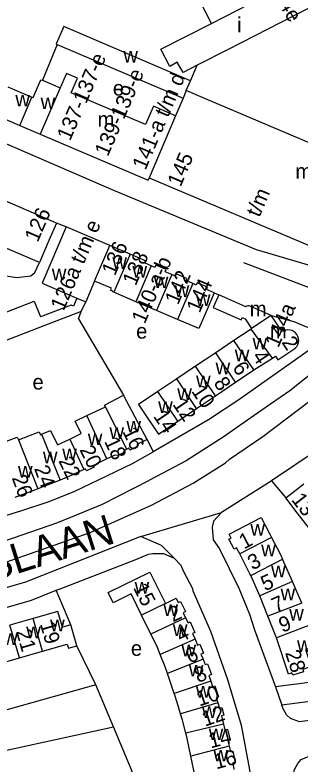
# Model space of a CAD drawing. Extents: x 161141 to 163125, y 381621 to 383200.
# Drawn here: x 162277.6 to 162353, y 382444.3 to 382642.8 of the extents above; entities that cross this region are included whole.
import ezdxf

# ---------------------------------------------------------------- set-up
doc = ezdxf.new("R2010")
doc.units = 0
for name, color, linetype in [('BLT_Basislijn', 7, 'Continuous'), ('BLT_Bebouwing', 7, 'Continuous'), ('BLT_Centroide', 7, 'Continuous'), ('BLT_Huisnummer', 7, 'Continuous'), ('BLT_Huisnummer_ tussenligend', 7, 'Continuous'), ('BLT_Huisnummer_reeks', 7, 'Continuous'), ('BLT_Onderdoorgang_en_onderverdeling', 7, 'Continuous'), ('BLT_Onderverdeling_panden', 7, 'Continuous'), ('BLT_Straatnaam_hoofdweg', 7, 'Continuous'), ('BLT_Vlakafsluiter', 7, 'Continuous')]:
    doc.layers.add(name, color=color, linetype=linetype)

msp = doc.modelspace()

# ---------------------------------------------------------------- linework, layer by layer
at = {"layer": 'BLT_Basislijn'}
for p, q in [((162288.77, 382634.99), (162284.83, 382625.47)), ((162324.01, 382625.3), (162325.78, 382629.45)), ((162291.14, 382586.62), (162288.54, 382587.63)), ((162338.06, 382577.23), (162368.49, 382565.55)), ((162330.3, 382569.18), (162331.49, 382568.61)), ((162294.42, 382562.3), (162295.1, 382564.25)), ((162294.42, 382562.3), (162306.27, 382542.03)), ((162312.57, 382530.29), (162314.16, 382527.02)), ((162345.48, 382519.35), (162349.25, 382514.86)), ((162288.51, 382490.36), (162289.53, 382490.77)), ((162292.32, 382481.23), (162288.51, 382490.36)), ((162298.98, 382465.34), (162293.93, 382475.68)), ((162303.64, 382454.22), (162298.98, 382465.34)), ((162346.52, 382464.77), (162348.22, 382459.93)), ((162255.7, 382443.65), (162303.64, 382454.22)), ((162314.81, 382427.53), (162303.64, 382454.22))]:
    msp.add_line(p, q, dxfattribs=at)
for points in [[(162377.15, 382570.34), (162374.71, 382570.72), (162341.47, 382580.52), (162303.7, 382596.26), (162245.74, 382621.4), (162216.51, 382633.67)], [(162270.38, 382574.4), (162278.09, 382573.22), (162281.73, 382573.67), (162282.87, 382574.53), (162284.03, 382577.2)], [(162345.42, 382563.14), (162351.37, 382561.53), (162356.87, 382559.29)], [(162359.01, 382556.56), (162337.09, 382541.02), (162328.81, 382535.56), (162314.16, 382527.02)], [(162362.6, 382553.21), (162361.54, 382552.11), (162350.35, 382543.18), (162342.61, 382537.88), (162332.63, 382530.95), (162322.85, 382524.63), (162313.17, 382519.51)], [(162080.89, 382389.1), (162087.08, 382392.8), (162096.77, 382401.05), (162097.06, 382401.61), (162097.92, 382402.29), (162103.21, 382407.77), (162109.43, 382414.56), (162120.5, 382427.73), (162125.96, 382433.33), (162133.78, 382441.38), (162141.36, 382447.96), (162147.08, 382452.5), (162159.07, 382460.25), (162172.83, 382467.15), (162180.96, 382470.1), (162190.27, 382472.7), (162275.19, 382497.81), (162297.47, 382505.64), (162313.73, 382512.88), (162324.73, 382518.77), (162333.27, 382524.13), (162334.37, 382525.07), (162343.16, 382531.08), (162361.67, 382545.16)], [(162383.83, 382545.11), (162378.38, 382544.88), (162376.37, 382543.54), (162375.25, 382542.27), (162369.73, 382537.16), (162363.18, 382531.84), (162358.04, 382527.86), (162345.48, 382519.35)], [(162172.61, 382477.74), (162186.12, 382483.3), (162199.16, 382487.35), (162253.43, 382503.47), (162279.4, 382511.46), (162286.35, 382513.81), (162293.23, 382516.51), (162308.69, 382523.97), (162314.16, 382527.02)], [(162165.32, 382469.27), (162183.81, 382476.93), (162207.64, 382483.85), (162227, 382489.35), (162247.17, 382495.26), (162272.22, 382502.6), (162288.93, 382508.3), (162300.74, 382513.19), (162313.17, 382519.51)], [(162345.48, 382519.35), (162345.35, 382519.26), (162332.22, 382510.96)], [(162332.22, 382510.96), (162330.15, 382508.67), (162329.74, 382507.12), (162329.99, 382503.73), (162331.74, 382501.34), (162336.79, 382490.88), (162339.65, 382484.06), (162340.97, 382479.9), (162346.52, 382464.77)], [(162310.85, 382504.64), (162280.32, 382492.48), (162199.17, 382469.05)], [(162319.72, 382498.85), (162316.34, 382502.26), (162310.85, 382504.64)], [(162289.53, 382490.77), (162309.58, 382498.47), (162311.26, 382499.2)], [(162311.26, 382499.2), (162312.93, 382499.93), (162314.05, 382500.14), (162316.85, 382500.06), (162319.72, 382498.85)], [(162319.72, 382498.85), (162321.48, 382496.97), (162322.07, 382495.5), (162324.57, 382490.82), (162324.65, 382490.19), (162329.36, 382479.49), (162333.84, 382466.74), (162337.48, 382454.61), (162339.66, 382442.79), (162340.26, 382437.31)], [(162230.37, 382472.85), (162281.95, 382487.74), (162288.51, 382490.36)], [(162464.97, 382470.2), (162464.33, 382475.08), (162348.22, 382459.93)], [(162464.97, 382470.2), (162352.84, 382455.52), (162350.45, 382456.39), (162349.43, 382457.35), (162348.52, 382458.94), (162348.22, 382459.93)], [(162369.65, 382467.77), (162369.4, 382467.73), (162346.52, 382464.77)], [(162298.98, 382465.34), (162237.44, 382448.02)], [(162353.18, 382419.2), (162353.09, 382419.93), (162351.56, 382433.33), (162350.83, 382439.71), (162351.54, 382442.89), (162352.39, 382444.47), (162353.32, 382445.55), (162356.51, 382446.83), (162364.73, 382448.34), (162398.2, 382452.33), (162399.64, 382452.33), (162402.4, 382451.37), (162403.22, 382450.61), (162405.69, 382446.67), (162407.37, 382433.33), (162408.28, 382426.15)]]:
    msp.add_lwpolyline(points, dxfattribs=at)
at = {"layer": 'BLT_Bebouwing'}
for p, q in [((162329.59, 382640.56), (162326.41, 382646.79)), ((162288.77, 382634.99), (162322.06, 382620.7)), ((162275.73, 382623.74), (162282.08, 382621.01)), ((162284.83, 382625.47), (162289.51, 382623.45)), ((162322.91, 382622.75), (162324.01, 382625.3)), ((162328, 382620.59), (162322.91, 382622.75)), ((162278.85, 382613.51), (162282.08, 382621.01)), ((162322.06, 382620.7), (162320.1, 382616.1)), ((162272.48, 382616.2), (162278.85, 382613.51)), ((162288.54, 382587.63), (162264.79, 382597.91)), ((162313.1, 382599.64), (162368.46, 382576.15)), ((162284.03, 382577.2), (162260.27, 382587.47)), ((162302.68, 382581.69), (162291.14, 382586.62)), ((162308.04, 382579.41), (162302.68, 382581.69)), ((162298.65, 382572.27), (162296.31, 382566.78)), ((162303.13, 382570.36), (162298.65, 382572.27)), ((162338.67, 382565.49), (162331.49, 382568.61)), ((162246.2, 382552.82), (162282.68, 382566.95)), ((162282.68, 382566.95), (162284.3, 382562.77)), ((162295.1, 382564.25), (162296.31, 382566.78)), ((162315.02, 382564.49), (162309.56, 382566.82)), ((162295.1, 382564.25), (162285.2, 382560.44)), ((162320.57, 382562.12), (162315.02, 382564.49)), ((162345.42, 382563.14), (162339.81, 382565.66)), ((162348.27, 382558.89), (162345.42, 382563.14)), ((162285.2, 382560.44), (162254, 382548.36)), ((162340.05, 382559.57), (162335.54, 382556.54)), ((162340.21, 382559.68), (162340.05, 382559.57)), ((162335.54, 382556.54), (162330.71, 382553.29)), ((162330.71, 382553.29), (162325.38, 382549.7)), ((162340.79, 382548.73), (162345.71, 382551.86)), ((162325.38, 382549.7), (162320.38, 382546.34)), ((162335.96, 382545.49), (162340.79, 382548.73)), ((162320.38, 382546.34), (162315.4, 382542.99)), ((162330.63, 382541.9), (162335.96, 382545.49)), ((162325.65, 382538.55), (162330.63, 382541.9)), ((162296.6, 382536.67), (162301.49, 382539)), ((162320.65, 382535.19), (162325.65, 382538.55)), ((162284.62, 382531.69), (162286.97, 382532.67)), ((162289.5, 382519.57), (162283.64, 382517.2)), ((162349.25, 382514.86), (162354.02, 382518.54)), ((162351, 382492.7), (162348.4, 382498.61)), ((162342.4, 382488.92), (162339.96, 382494.3)), ((162353.52, 382486.97), (162351, 382492.7)), ((162344.53, 382483.52), (162342.4, 382488.92)), ((162282.35, 382482.86), (162276.22, 382481.08)), ((162313.56, 382478.77), (162311.08, 382483.78)), ((162346.82, 382477.73), (162344.53, 382483.52)), ((162278.73, 382472.42), (162284.86, 382474.2)), ((162319.71, 382463.01), (162317.93, 382468.29)), ((162319.86, 382462.55), (162319.71, 382463.01)), ((162323.03, 382451.51), (162322.77, 382452.5)), ((162324.12, 382446.43), (162323.03, 382451.51)), ((162325.29, 382440.96), (162324.12, 382446.43))]:
    msp.add_line(p, q, dxfattribs=at)
for points in [[(162355.84, 382644.86), (162351.39, 382642.58), (162334.16, 382633.75)], [(162324.01, 382625.3), (162290.47, 382639.7), (162288.5, 382635.1), (162288.77, 382634.99)], [(162325.78, 382629.45), (162322.08, 382627.56), (162320.52, 382630.27), (162318.55, 382629.13), (162316.2, 382633.71), (162329.59, 382640.56)], [(162334.16, 382633.75), (162325.78, 382629.45)], [(162282.08, 382621.01), (162282.39, 382620.88), (162284.44, 382625.64), (162284.83, 382625.47)], [(162320.1, 382616.1), (162314.23, 382618.61), (162312.14, 382613.75), (162292.46, 382622.19), (162294.11, 382626.04), (162291.18, 382627.3), (162289.51, 382623.45)], [(162379.03, 382608.25), (162375.86, 382604.38), (162373.38, 382601.34), (162328, 382620.59)], [(162278.85, 382613.51), (162284.25, 382611.21)], [(162284.25, 382611.21), (162312.83, 382599), (162313.1, 382599.64)], [(162288.54, 382587.63), (162286.56, 382583.04), (162284.03, 382577.2)], [(162291.14, 382586.62), (162284.77, 382571.71), (162293.94, 382567.79)], [(162313.62, 382576.33), (162311.87, 382577.07), (162312.13, 382577.66), (162308.04, 382579.41)], [(162319.07, 382573.99), (162317.35, 382574.73), (162317.61, 382575.33), (162314.85, 382576.5), (162314.59, 382575.91), (162313.62, 382576.33)], [(162324.64, 382571.62), (162322.84, 382572.39), (162323.09, 382572.99), (162320.24, 382574.2), (162319.99, 382573.6), (162319.07, 382573.99)], [(162303.73, 382569.31), (162303.38, 382569.47), (162303.45, 382569.59), (162302.9, 382569.83), (162303.13, 382570.36)], [(162330.3, 382569.18), (162328.3, 382570.03), (162328.56, 382570.63), (162325.81, 382571.8), (162325.57, 382571.23), (162324.64, 382571.62)], [(162309.56, 382566.82), (162303.73, 382569.31)], [(162330.3, 382569.18), (162328.34, 382564.58), (162326.25, 382559.7), (162320.57, 382562.12)], [(162331.49, 382568.61), (162330.03, 382565.24), (162337.44, 382562.02), (162337.7, 382562.61), (162338.54, 382562.24), (162340.21, 382559.68)], [(162293.94, 382567.79), (162293.04, 382565.67), (162292.45, 382565.93), (162284.3, 382562.77)], [(162339.81, 382565.66), (162339.49, 382565.72), (162339.17, 382565.7), (162338.86, 382565.6), (162338.67, 382565.49)], [(162351.41, 382554.22), (162351.81, 382554.55), (162352.16, 382554.96), (162352.45, 382555.49), (162352.61, 382556.05), (162352.66, 382556.55), (162352.6, 382557.11), (162352.46, 382557.6), (162352.18, 382558.13), (162351.85, 382558.54), (162351.44, 382558.87), (162350.95, 382559.15), (162350.43, 382559.31), (162349.83, 382559.37), (162349.27, 382559.31), (162348.72, 382559.13), (162348.27, 382558.89)], [(162345.71, 382551.86), (162346.5, 382552.39), (162347.18, 382551.38), (162351.41, 382554.22)], [(162315.4, 382542.99), (162310.3, 382539.56), (162312.75, 382535.9), (162315.54, 382531.75), (162320.65, 382535.19)], [(162301.49, 382539), (162301.31, 382539.37), (162306.27, 382542.03)], [(162312.57, 382530.29), (162310.2, 382534.7), (162306.27, 382542.03)], [(162292.06, 382530.43), (162295.09, 382531.88), (162293.51, 382535.18), (162296.6, 382536.67)], [(162278.47, 382530.19), (162284.02, 382532.34), (162284.35, 382531.58), (162284.62, 382531.69)], [(162286.97, 382532.67), (162288.8, 382528.86), (162292.06, 382530.43)], [(162273.59, 382527.57), (162273.13, 382529.05), (162278.19, 382530.89), (162278.47, 382530.19)], [(162312.57, 382530.29), (162309.84, 382528.99), (162310.06, 382528.54), (162307.94, 382527.52), (162307.72, 382527.97), (162307.18, 382527.71)], [(162307.18, 382527.71), (162306.63, 382527.44), (162306.1, 382526.67), (162304.91, 382526.1), (162304.02, 382526.16), (162301.89, 382525.14)], [(162301.89, 382525.14), (162298.35, 382523.44), (162298.55, 382523.02), (162296.49, 382522.03), (162296.24, 382522.57), (162295.79, 382522.35)], [(162295.79, 382522.35), (162292.66, 382520.85), (162289.5, 382519.57)], [(162283.64, 382517.2), (162283.47, 382517.14), (162277.5, 382514.97)], [(162355.42, 382506.85), (162352.3, 382510.9), (162349.25, 382514.86)], [(162337.08, 382499.97), (162336.21, 382501.57), (162335.57, 382501.23), (162334.19, 382503.86), (162334.81, 382504.19), (162334.26, 382505.24), (162342.71, 382509.68), (162345.04, 382505.25), (162345.49, 382504.38)], [(162345.49, 382504.38), (162347.79, 382500), (162348.4, 382498.61)], [(162339.96, 382494.3), (162339.85, 382494.54), (162337.08, 382499.97)], [(162311.08, 382483.78), (162308.29, 382489.42), (162303.53, 382487.05), (162302.26, 382489.75), (162313.27, 382495.2), (162317.38, 382486.89)], [(162317.38, 382486.89), (162320.26, 382488.27), (162320.78, 382487.12), (162321.38, 382487.37), (162322.68, 382484.71), (162322.11, 382484.41), (162322.74, 382483.06)], [(162292.32, 382481.23), (162290.11, 382480.59), (162288.9, 382484.76), (162282.35, 382482.86)], [(162322.74, 382483.06), (162323.37, 382481.72), (162323.98, 382481.97), (162325.18, 382479.19), (162324.57, 382478.93), (162325.25, 382477.38)], [(162293.93, 382475.68), (162292.32, 382481.23)], [(162355.75, 382481.16), (162356.04, 382480.42), (162357.63, 382475.68), (162354.43, 382474.71), (162355.93, 382470.18), (162353.73, 382469.36), (162353.95, 382468.78), (162351.08, 382467.85), (162350.85, 382468.46), (162349.99, 382468.17), (162346.82, 382477.73)], [(162316.01, 382473.37), (162315.09, 382475.67), (162313.56, 382478.77)], [(162325.25, 382477.38), (162325.92, 382475.83), (162326.48, 382476.09), (162327.43, 382473.68), (162326.78, 382473.47), (162327.35, 382472.07)], [(162284.86, 382474.2), (162291.42, 382476.1), (162291.72, 382475.04), (162293.93, 382475.68)], [(162317.93, 382468.29), (162317.33, 382470.06), (162316.01, 382473.37)], [(162272.64, 382470.65), (162278.73, 382472.42)], [(162327.35, 382472.07), (162327.91, 382470.66), (162328.53, 382470.88), (162329.61, 382468.04), (162328.92, 382467.74), (162329.41, 382466.31)], [(162329.41, 382466.31), (162329.89, 382464.89), (162330.5, 382465.07), (162331.42, 382462.16), (162330.81, 382461.98), (162331.24, 382460.56)], [(162321.42, 382457.59), (162320.49, 382460.62), (162319.86, 382462.55)], [(162331.24, 382460.56), (162331.67, 382459.14), (162332.29, 382459.29), (162332.83, 382457.31), (162332.24, 382457.13), (162332.77, 382454.86)], [(162322.77, 382452.5), (162321.89, 382455.96), (162321.42, 382457.59)], [(162332.77, 382454.86), (162333.13, 382453.38), (162333.83, 382453.57), (162334.49, 382450.62), (162333.89, 382450.46), (162334.26, 382449.05)], [(162334.26, 382449.05), (162334.62, 382447.63), (162335.2, 382447.71), (162335.81, 382444.79), (162335.2, 382444.63), (162335.49, 382442.84)]]:
    msp.add_lwpolyline(points, dxfattribs=at)
at = {"layer": 'BLT_Onderdoorgang_en_onderverdeling'}
msp.add_line((162289.51, 382623.45), (162284.25, 382611.21), dxfattribs=at)
at = {"layer": 'BLT_Onderverdeling_panden'}
for p, q in [((162329.59, 382640.56), (162350.46, 382651.28)), ((162322.91, 382622.75), (162322.06, 382620.7)), ((162320.1, 382616.1), (162313.1, 382599.64)), ((162298.65, 382572.27), (162302.68, 382581.69)), ((162308.04, 382579.41), (162303.73, 382569.31)), ((162313.62, 382576.33), (162309.56, 382566.82)), ((162319.07, 382573.99), (162315.02, 382564.49)), ((162324.64, 382571.62), (162320.57, 382562.12)), ((162293.94, 382567.79), (162296.31, 382566.78)), ((162345.42, 382563.14), (162340.21, 382559.68)), ((162345.71, 382551.86), (162340.05, 382559.57)), ((162340.79, 382548.73), (162335.54, 382556.54)), ((162335.96, 382545.49), (162330.71, 382553.29)), ((162330.63, 382541.9), (162325.38, 382549.7)), ((162325.65, 382538.55), (162320.38, 382546.34)), ((162320.65, 382535.19), (162315.4, 382542.99)), ((162307.18, 382527.71), (162301.49, 382539)), ((162301.89, 382525.14), (162296.6, 382536.67)), ((162284.62, 382531.69), (162289.5, 382519.57)), ((162292.06, 382530.43), (162295.79, 382522.35)), ((162278.47, 382530.19), (162283.64, 382517.2)), ((162345.49, 382504.38), (162337.08, 382499.97)), ((162339.96, 382494.3), (162348.4, 382498.61)), ((162351, 382492.7), (162342.4, 382488.92)), ((162317.38, 382486.89), (162311.08, 382483.78)), ((162353.52, 382486.97), (162344.53, 382483.52)), ((162284.86, 382474.2), (162282.35, 382482.86)), ((162322.74, 382483.06), (162313.56, 382478.77)), ((162278.73, 382472.42), (162276.22, 382481.08)), ((162355.75, 382481.16), (162346.82, 382477.73)), ((162325.25, 382477.38), (162316.01, 382473.37)), ((162327.35, 382472.07), (162317.93, 382468.29)), ((162329.41, 382466.31), (162319.71, 382463.01)), ((162331.24, 382460.56), (162321.42, 382457.59)), ((162332.77, 382454.86), (162322.77, 382452.5)), ((162334.26, 382449.05), (162324.12, 382446.43))]:
    msp.add_line(p, q, dxfattribs=at)
at = {"layer": 'BLT_Vlakafsluiter'}
msp.add_line((162310.85, 382504.64), (162332.22, 382510.96), dxfattribs=at)

# ---------------------------------------------------------------- texts
at = {"layer": 'BLT_Centroide'}
for s, p in [('i', (162336.35, 382638.2)), ('w', (162306.26, 382630.19)), ('e', (162303.49, 382621.42)), ('w', (162277.67, 382618.55)), ('w', (162284.35, 382617.83)), ('m', (162299.45, 382613.16)), ('m', (162351.78, 382599.38)), ('w', (162303.34, 382575.52)), ('w', (162308.67, 382573.16)), ('w', (162287.33, 382572.46)), ('w', (162314.31, 382570.41)), ('w', (162319.83, 382568.05)), ('w', (162325.44, 382565.66)), ('m', (162339.71, 382562.95)), ('e', (162309.64, 382557.04)), ('m', (162345.01, 382557.12)), ('w', (162340.45, 382554.17)), ('w', (162335.75, 382551.02)), ('w', (162330.67, 382547.59)), ('e', (162282.22, 382543.54)), ('w', (162325.5, 382544.16)), ('w', (162320.53, 382540.75)), ('w', (162315.47, 382537.36)), ('w', (162307.08, 382532.17)), ('w', (162302.58, 382530.47)), ('w', (162296.86, 382528.81)), ('w', (162284.97, 382524)), ('w', (162290.09, 382524.8)), ('w', (162278.38, 382520.22)), ('w', (162339.87, 382504.81)), ('w', (162342.73, 382499.34)), ('w', (162345.37, 382493.78)), ('w', (162309.24, 382489.5)), ('w', (162347.87, 382487.72)), ('w', (162316.86, 382483.53)), ('w', (162350.15, 382482.34)), ('w', (162280.55, 382477.64)), ('w', (162286.88, 382479.47)), ('w', (162319.36, 382478.22)), ('w', (162274.44, 382475.88)), ('w', (162352.22, 382474.02)), ('e', (162308.25, 382472.99)), ('w', (162321.64, 382472.84)), ('w', (162323.59, 382467.53)), ('w', (162325.44, 382461.94)), ('w', (162327.05, 382456.53)), ('w', (162328.85, 382450.66)), ('w', (162330.09, 382445))]:
    msp.add_text(s, height=4, dxfattribs=at).set_placement(p)
at = {"layer": 'BLT_Huisnummer'}
for s, rotation, p in [('126', 66.5937, (162283.6, 382582.38)), ('136', 66.8844, (162304.02, 382573.49)), ('144', 66.8812, (162326.44, 382563.61)), ('6', 303.9147, (162334.98, 382549.33)), ('10', 303.9114, (162324.12, 382543.12)), ('14', 303.9139, (162314.05, 382536.45)), ('16', 295.6589, (162305.92, 382532.47)), ('20', 295.6536, (162294.58, 382527.65)), ('24', 290.0263, (162282.58, 382522.66)), ('13', 307.6177, (162350.56, 382514.32)), ('1', 27.6979, (162338.18, 382501.14)), ('5', 23.7426, (162343.73, 382490.07)), ('15', 296.3311, (162308.77, 382491.07)), ('2', 25.0647, (162319.36, 382481.83)), ('9', 20.9864, (162348.31, 382479.08)), ('19', 286.1829, (162284.14, 382481.48)), ('6', 21.8622, (162323.75, 382470.89)), ('28', 288.2934, (162349.01, 382473.83)), ('10', 18.8205, (162326.39, 382459.54)), ('14', 14.4582, (162329.38, 382448.46))]:
    msp.add_text(s, height=4, rotation=rotation, dxfattribs=at).set_placement(p)
at = {"layer": 'BLT_Huisnummer_ tussenligend'}
for s, rotation, p in [('138', 66.8844, (162309.53, 382570.85)), ('142', 66.8859, (162320.73, 382565.79)), ('4', 303.9146, (162340.21, 382552.3)), ('8', 303.9147, (162330.01, 382545.27)), ('12', 303.9114, (162319.15, 382539.62)), ('18', 295.6589, (162301.1, 382529.82)), ('22', 295.6536, (162288.99, 382524.68)), ('26', 290.0263, (162276.68, 382520.17)), ('3', 27.6979, (162340.45, 382495.58)), ('7', 23.7426, (162346.59, 382484.3)), ('4', 25.0647, (162321.4, 382476.48)), ('21', 286.1829, (162277.81, 382479.47)), ('8', 21.8622, (162326.02, 382465.75)), ('12', 18.8205, (162327.84, 382454.2)), ('16', 14.4582, (162330.82, 382442.91))]:
    msp.add_text(s, height=4, rotation=rotation, dxfattribs=at).set_placement(p)
at = {"layer": 'BLT_Huisnummer_reeks'}
for s, rotation, p in [('54e', 299.9932, (162345.83, 382648.24)), ('137-137-e', 66.6527, (162292.15, 382609.23)), ('139-139-e', 66.6527, (162302.15, 382605.09)), ('141-a t/m d', 66.9684, (162312.12, 382601.48)), ('145', 66.9684, (162321.4, 382597.03)), ('t/m', 66.9684, (162342.26, 382588.99)), ('126a t/m e', 66.872, (162290.47, 382564.19)), ('140-a-b', 66.8859, (162311.92, 382560.73)), ('144a', 66.8737, (162347.27, 382554.41)), ('2', 303.9146, (162348.01, 382556.04))]:
    msp.add_text(s, height=4, rotation=rotation, dxfattribs=at).set_placement(p)
at = {"layer": 'BLT_Straatnaam_hoofdweg'}
msp.add_text('ST JORISLAAN', height=8, rotation=17.5292, dxfattribs=at).set_placement((162231.93, 382480.08))

doc.saveas('drawing.dxf')
